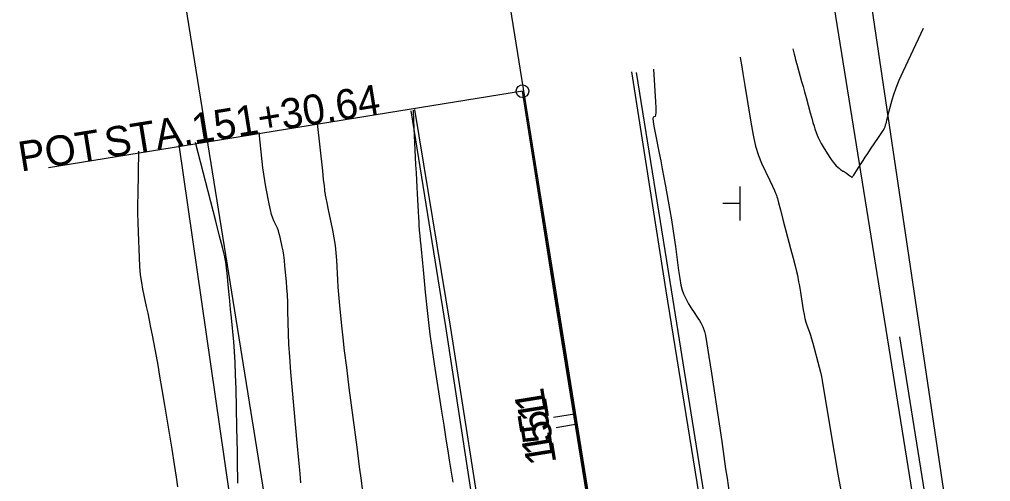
# Model space of a CAD drawing. Extents: x 2030588 to 2035216, y 462285 to 465007.
# Drawn here: x 2031156.3 to 2031247.3, y 464572.4 to 464615.7 of the extents above; entities that cross this region are included whole.
import ezdxf

# ---------------------------------------------------------------- set-up
doc = ezdxf.new("R2010")
doc.units = 0
for name, color, linetype in [('DT_X_Contour_Minor', 7, 'Continuous'), ('GE_X_Alignment', 7, 'Continuous'), ('GE_X_Alignment_100_Cardinal_Points', 7, 'Continuous'), ('GE_X_Alignment_100_Stations', 7, 'Continuous'), ('PV_X_COP', 7, 'Continuous'), ('PV_X_EOP', 7, 'Continuous'), ('PV_X_Shoulder_Aggregate', 7, 'Continuous'), ('RW_X_CL', 7, 'Continuous'), ('RW_X_CL_100_Stations', 7, 'Continuous'), ('RW_X_Esmt_SH', 7, 'Continuous'), ('SN_X_Public', 7, 'Continuous'), ('UT_X_Cable_TV', 7, 'Continuous'), ('UT_X_Electric', 7, 'Continuous'), ('VG_X_Tree_Line_Lt', 7, 'Continuous')]:
    doc.layers.add(name, color=color, linetype=linetype)

msp = doc.modelspace()

# ---------------------------------------------------------------- linework, layer by layer
at = {"layer": 'DT_X_Contour_Minor'}
for points in [[(2031228.797, 464612.906), (2031228.88, 464612.528), (2031228.911, 464612.402), (2031228.969, 464612.185), (2031229.052, 464611.878), (2031229.162, 464611.481), (2031229.49, 464610.301), (2031229.616, 464609.846), (2031229.749, 464609.369), (2031229.887, 464608.868), (2031230.031, 464608.343), (2031230.424, 464606.914), (2031230.562, 464606.417), (2031230.682, 464606.001), (2031230.783, 464605.664), (2031230.866, 464605.407), (2031231.063, 464604.828), (2031231.154, 464604.596), (2031231.279, 464604.335), (2031231.438, 464604.044), (2031231.631, 464603.724), (2031232.191, 464602.832), (2031232.389, 464602.526), (2031232.564, 464602.278), (2031232.715, 464602.088), (2031232.843, 464601.956), (2031233.153, 464601.681), (2031233.259, 464601.59), (2031233.343, 464601.522), (2031233.407, 464601.477), (2031233.45, 464601.456), (2031233.537, 464601.43), (2031233.579, 464601.411), (2031233.64, 464601.375), (2031233.72, 464601.32), (2031233.82, 464601.248), (2031234.112, 464601.031), (2031234.209, 464600.962), (2031234.282, 464600.916), (2031234.332, 464600.893), (2031234.358, 464600.893), (2031234.395, 464600.926), (2031234.428, 464600.969), (2031234.498, 464601.074), (2031234.606, 464601.239), (2031234.752, 464601.467), (2031235.192, 464602.155), (2031235.371, 464602.432), (2031235.579, 464602.748), (2031235.815, 464603.102), (2031236.08, 464603.494), (2031236.825, 464604.592), (2031237.073, 464604.965), (2031237.258, 464605.259), (2031237.381, 464605.474), (2031237.441, 464605.611), (2031237.519, 464605.871), (2031237.559, 464606.012), (2031237.619, 464606.24), (2031237.7, 464606.554), (2031237.802, 464606.956), (2031238.101, 464608.141), (2031238.25, 464608.639), (2031238.472, 464609.243), (2031238.767, 464609.954), (2031239.136, 464610.772), (2031241.027, 464614.837)], [(2031223.862, 464612.11), (2031223.867, 464612.077), (2031223.894, 464611.909), (2031223.973, 464611.419), (2031224.104, 464610.608), (2031224.287, 464609.475), (2031224.846, 464606.025), (2031225.065, 464604.817), (2031225.305, 464603.777), (2031225.566, 464602.908), (2031225.847, 464602.208), (2031226.623, 464600.567), (2031226.879, 464600.027), (2031227.063, 464599.637), (2031227.175, 464599.397), (2031227.216, 464599.308), (2031227.231, 464599.269), (2031227.237, 464599.251), (2031227.245, 464599.226), (2031227.256, 464599.194), (2031227.269, 464599.155), (2031227.305, 464599.042), (2031227.351, 464598.878), (2031227.46, 464598.47), (2031227.633, 464597.818), (2031227.87, 464596.923), (2031228.587, 464594.212), (2031228.827, 464593.293), (2031229.013, 464592.569), (2031229.142, 464592.041), (2031229.216, 464591.708), (2031229.338, 464591.081), (2031229.387, 464590.818), (2031229.443, 464590.498), (2031229.506, 464590.12), (2031229.576, 464589.686), (2031229.771, 464588.453), (2031229.847, 464588.018), (2031229.927, 464587.635), (2031230.012, 464587.306), (2031230.102, 464587.031), (2031230.349, 464586.367), (2031230.446, 464586.087), (2031230.554, 464585.745), (2031230.671, 464585.342), (2031230.798, 464584.876), (2031231.15, 464583.552), (2031231.274, 464583.072), (2031231.379, 464582.625), (2031231.467, 464582.211), (2031231.537, 464581.83), (2031231.701, 464580.858), (2031231.787, 464580.35), (2031231.922, 464579.555), (2031232.106, 464578.473), (2031232.339, 464577.104), (2031233.026, 464573.072), (2031233.284, 464571.539)], [(2031215.741, 464610.999), (2031215.925, 464607.941), (2031215.952, 464607.364), (2031215.953, 464606.943), (2031215.929, 464606.679), (2031215.88, 464606.571), (2031215.713, 464606.493), (2031215.677, 464606.379), (2031215.693, 464606.097), (2031215.76, 464605.645), (2031215.88, 464605.024), (2031216.268, 464603.143), (2031216.414, 464602.419), (2031216.561, 464601.659), (2031216.71, 464600.861), (2031216.861, 464600.026), (2031217.264, 464597.75), (2031217.409, 464596.899), (2031217.545, 464596.052), (2031217.67, 464595.21), (2031217.785, 464594.371), (2031218.076, 464592.142), (2031218.188, 464591.378), (2031218.304, 464590.759), (2031218.425, 464590.285), (2031218.551, 464589.956), (2031218.892, 464589.273), (2031219.024, 464589.019), (2031219.165, 464588.772), (2031219.314, 464588.531), (2031219.472, 464588.295), (2031219.905, 464587.676), (2031220.055, 464587.452), (2031220.179, 464587.243), (2031220.277, 464587.049), (2031220.35, 464586.87), (2031220.511, 464586.414), (2031220.597, 464586.042), (2031220.734, 464585.267), (2031220.924, 464584.09), (2031221.165, 464582.51), (2031221.878, 464577.762), (2031222.125, 464576.108), (2031222.332, 464574.708), (2031222.498, 464573.562), (2031222.625, 464572.67), (2031222.907, 464570.63)], [(2031193.204, 464607.156), (2031193.24, 464606.217), (2031193.247, 464606.034), (2031193.253, 464605.89), (2031193.258, 464605.784), (2031193.263, 464605.716), (2031193.28, 464605.488), (2031193.443, 464602.029), (2031193.478, 464601.302), (2031193.513, 464600.606), (2031193.548, 464599.941), (2031193.583, 464599.306), (2031193.676, 464597.652), (2031193.707, 464597.1), (2031193.731, 464596.683), (2031193.747, 464596.402), (2031193.755, 464596.257), (2031193.768, 464596.05), (2031193.773, 464595.978), (2031193.777, 464595.918), (2031193.78, 464595.868), (2031193.783, 464595.831), (2031193.79, 464595.745), (2031193.8, 464595.64), (2031193.824, 464595.39), (2031193.863, 464594.994), (2031193.915, 464594.453), (2031194.074, 464592.815), (2031194.136, 464592.185), (2031194.202, 464591.521), (2031194.272, 464590.824), (2031194.346, 464590.094), (2031194.549, 464588.104), (2031194.646, 464587.251), (2031194.786, 464586.183), (2031194.968, 464584.902), (2031195.192, 464583.406), (2031195.847, 464579.133), (2031196.077, 464577.634), (2031196.277, 464576.341), (2031196.447, 464575.254), (2031196.586, 464574.374), (2031196.916, 464572.301)], [(2031184.221, 464605.899), (2031184.7, 464601.486), (2031184.791, 464600.656), (2031184.857, 464600.054), (2031184.898, 464599.682), (2031184.915, 464599.54), (2031184.929, 464599.465), (2031184.933, 464599.438), (2031184.937, 464599.413), (2031184.94, 464599.39), (2031184.942, 464599.369), (2031184.948, 464599.314), (2031184.968, 464599.207), (2031185.025, 464598.923), (2031185.119, 464598.465), (2031185.249, 464597.832), (2031185.646, 464595.909), (2031185.78, 464595.192), (2031185.887, 464594.485), (2031185.966, 464593.788), (2031186.017, 464593.099), (2031186.115, 464591.276), (2031186.155, 464590.592), (2031186.204, 464589.905), (2031186.262, 464589.216), (2031186.327, 464588.526), (2031186.512, 464586.682), (2031186.606, 464585.816), (2031186.751, 464584.603), (2031186.947, 464583.042), (2031187.193, 464581.134), (2031187.917, 464575.582), (2031188.154, 464573.758), (2031188.325, 464572.45), (2031188.429, 464571.66)], [(2031182.676, 464572.241), (2031182.606, 464573.112), (2031182.497, 464574.368), (2031182.348, 464576.009), (2031181.9, 464580.899), (2031181.751, 464582.605), (2031181.638, 464584.056), (2031181.564, 464585.252), (2031181.526, 464586.193), (2031181.475, 464588.361), (2031181.452, 464589.141), (2031181.421, 464589.856), (2031181.381, 464590.506), (2031181.333, 464591.091), (2031181.195, 464592.563), (2031181.14, 464593.089), (2031181.08, 464593.561), (2031181.014, 464593.981), (2031180.942, 464594.347), (2031180.744, 464595.253), (2031180.666, 464595.574), (2031180.584, 464595.856), (2031180.496, 464596.099), (2031180.403, 464596.303), (2031180.147, 464596.796), (2031180.049, 464597.034), (2031179.945, 464597.375), (2031179.835, 464597.82), (2031179.721, 464598.37), (2031179.408, 464599.974), (2031179.298, 464600.573), (2031179.203, 464601.167), (2031179.123, 464601.756), (2031179.058, 464602.341), (2031178.789, 464605.056)], [(2031176.784, 464572.229), (2031176.774, 464572.668), (2031176.756, 464573.876), (2031176.747, 464574.44), (2031176.732, 464575.228), (2031176.712, 464576.24), (2031176.686, 464577.475), (2031176.609, 464581.065), (2031176.574, 464582.35), (2031176.526, 464583.509), (2031176.465, 464584.544), (2031176.391, 464585.454), (2031176.177, 464587.715), (2031176.1, 464588.523), (2031176.03, 464589.252), (2031175.967, 464589.902), (2031175.91, 464590.474), (2031175.77, 464591.892), (2031175.723, 464592.358), (2031175.689, 464592.694), (2031175.666, 464592.9), (2031175.655, 464592.975), (2031175.642, 464593), (2031175.635, 464593.019), (2031175.626, 464593.057), (2031175.614, 464593.113), (2031175.599, 464593.187), (2031175.555, 464593.411), (2031175.49, 464593.682), (2031175.327, 464594.328), (2031175.066, 464595.349), (2031174.708, 464596.744), (2031172.808, 464604.13)], [(2031167.483, 464603.323), (2031167.398, 464599.255), (2031167.387, 464598.38), (2031167.388, 464597.502), (2031167.403, 464596.619), (2031167.43, 464595.731), (2031167.522, 464593.359), (2031167.568, 464592.505), (2031167.639, 464591.723), (2031167.734, 464591.014), (2031167.853, 464590.376), (2031168.202, 464588.772), (2031168.335, 464588.153), (2031168.469, 464587.5), (2031168.605, 464586.813), (2031168.743, 464586.092), (2031169.113, 464584.122), (2031169.266, 464583.281), (2031169.449, 464582.236), (2031169.66, 464580.987), (2031169.899, 464579.534), (2031170.577, 464575.388), (2031170.809, 464573.961), (2031170.995, 464572.789), (2031171.136, 464571.874)]]:
    msp.add_lwpolyline(points, dxfattribs=at)
at = {"layer": 'GE_X_Alignment'}
msp.add_line((2031257.417, 464274.275), (2031203.458, 464608.932), dxfattribs=at)
at = {"layer": 'GE_X_Alignment_100_Cardinal_Points'}
msp.add_line((2031203.458, 464608.932), (2031159.036, 464601.771), dxfattribs=at)
msp.add_ellipse((2031203.458, 464608.932), major_axis=(-0.401, 0.447), ratio=0.999987, dxfattribs=at)
at = {"layer": 'GE_X_Alignment_100_Stations'}
msp.add_line((2031208.335, 464578.685), (2031206.36, 464578.367), dxfattribs=at)
at = {"layer": 'PV_X_COP'}
msp.add_lwpolyline([(2031239.82, 464378.918), (2031237.293, 464394.23), (2031234.003, 464414.133), (2031230.523, 464435.72), (2031227.064, 464457.778), (2031223.868, 464479.049), (2031220.406, 464500.853), (2031217.211, 464522.279), (2031213.78, 464544.162), (2031210.249, 464566.426), (2031206.677, 464588.5), (2031203.458, 464608.932)], dxfattribs=at)
at = {"layer": 'PV_X_EOP'}
for points in [[(2031251.659, 464369.871), (2031250.509, 464376.276), (2031247.249, 464396.032), (2031243.946, 464415.746), (2031240.612, 464437.401), (2031237.044, 464459.528), (2031233.886, 464480.648), (2031230.49, 464502.512), (2031227.303, 464523.941), (2031223.954, 464545.798), (2031220.507, 464568.023), (2031216.931, 464590.234), (2031213.717, 464610.744)], [(2031220.382, 464434.076), (2031216.941, 464456.075), (2031213.647, 464477.618), (2031210.384, 464499.249), (2031206.925, 464520.754), (2031203.594, 464542.743), (2031200.181, 464564.746), (2031196.702, 464586.93), (2031193.38, 464607.224)]]:
    msp.add_lwpolyline(points, dxfattribs=at)
at = {"layer": 'PV_X_Shoulder_Aggregate'}
for points in [[(2031244.492, 464415.82), (2031241.204, 464437.394), (2031237.839, 464459.628), (2031234.469, 464480.77), (2031231.106, 464502.608), (2031227.919, 464524.008), (2031224.491, 464545.891), (2031220.992, 464568.078), (2031217.437, 464590.336), (2031214.143, 464610.697)], [(2031218.4, 464433.793), (2031218.362, 464445.956), (2031216.75, 464456.065), (2031213.473, 464477.522), (2031210.091, 464499.185), (2031206.658, 464520.675), (2031203.21, 464542.688), (2031199.691, 464564.683), (2031196.272, 464586.901), (2031193.023, 464607.086)]]:
    msp.add_lwpolyline(points, dxfattribs=at)
at = {"layer": 'RW_X_CL'}
msp.add_line((2031264.454, 464230.531), (2031192.714, 464676.453), dxfattribs=at)
at = {"layer": 'RW_X_CL_100_Stations'}
msp.add_line((2031208.596, 464577.732), (2031206.622, 464577.414), dxfattribs=at)
at = {"layer": 'RW_X_Esmt_SH'}
for p, q in [((2031294.07, 464235.295), (2031222.33, 464681.217)), ((2031234.838, 464225.767), (2031163.098, 464671.689))]:
    msp.add_line(p, q, dxfattribs=at)
at = {"layer": 'SN_X_Public'}
for p, q in [((2031223.834, 464600.018), (2031223.834, 464596.819)), ((2031223.834, 464598.418), (2031222.234, 464598.418)), ((2031223.833, 464598.419), (2031223.833, 464598.419))]:
    msp.add_line(p, q, dxfattribs=at)
at = {"layer": 'UT_X_Cable_TV'}
msp.add_lwpolyline([(2031238.795, 464585.928), (2031247.129, 464533.781), (2031254.05, 464490.196), (2031262.253, 464438.839), (2031269.698, 464392.26), (2031276.53, 464349.484), (2031283.448, 464306.226), (2031289.883, 464266.155)], dxfattribs=at)
at = {"layer": 'UT_X_Electric'}
msp.add_lwpolyline([(2031221.843, 464713.466), (2031231.941, 464645.283), (2031244.284, 464562.24), (2031252.852, 464504.34), (2031260, 464456.218), (2031264.868, 464423.288), (2031269.313, 464393.306), (2031274.036, 464361.48), (2031280.969, 464314.78), (2031288.221, 464265.917), (2031292.226, 464240.822), (2031300.292, 464190.304), (2031337.855, 463955.944)], dxfattribs=at)
at = {"layer": 'VG_X_Tree_Line_Lt'}
msp.add_lwpolyline([(2031171.252, 464603.925), (2031180.58, 464539.236), (2031190.567, 464478.707), (2031195.183, 464442.795), (2031200.666, 464404.618), (2031207.96, 464347.776), (2031213.537, 464319.454), (2031224.286, 464260.057), (2031224.633, 464250.708), (2031227.583, 464205.148)], dxfattribs=at)

# ---------------------------------------------------------------- texts
at = {"layer": 'GE_X_Alignment_100_Cardinal_Points'}
for s, p in [('151+30.64', (2031172.692, 464604.009)), (' STA. ', (2031163.489, 464602.526)), ('POT', (2031156.45, 464601.391))]:
    msp.add_text(s, height=2.7997, rotation=9.15866, dxfattribs=at).set_placement(p)
at = {"layer": 'GE_X_Alignment_100_Stations'}
msp.add_text('151', height=2.7997, rotation=99.15933, dxfattribs=at).set_placement((2031206.38, 464575.106))
at = {"layer": 'RW_X_CL_100_Stations'}
msp.add_text('151', height=2.7997, rotation=99.1395, dxfattribs=at).set_placement((2031206.64, 464574.153))

doc.saveas('drawing.dxf')
